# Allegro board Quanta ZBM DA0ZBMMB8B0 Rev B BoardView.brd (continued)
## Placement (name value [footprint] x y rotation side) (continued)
R3C22  20K_5%_2  [R0201-SMT-TEST]  87.97 42.06 0 top
R3C23  20K_5%_2  [R0201-SMT-TEST]  87.97 41.3 0 top
R3F3  56_1%_4  [R0402]  124.96 78.79 90 top
R3F4  100_1%_4  [R0402]  123.84 79.01 90 top
R3F13  *Short_0402  [S0402]  124.96 81.17 270 top
R4  0_5%_2  [R0201-SMT-TEST]  71.75 65.19 315 bottom
R4E63  *4.7K_1%_2  [R0201-SMT-TEST]  96.28 69.91 0 bottom
R4F20  *20K_1%_2  [R0201-SMT-TEST]  94.89 69.91 180 top
R4F23  100K_1%_2  [R0201-SMT-TEST]  94.76 70.62 0 top
R5  0_5%_2  [R0201-SMT-TEST]  72.92 66.36 315 bottom
R5F9  113_1%_2  [R0201-SMT-TEST]  105.9 77.35 180 top
R5G69  *1K_1%_2  [R0201-SMT-TEST]  119.65 76.68 270 top
R5M19  1K_1%_2  [R0201-SMT-TEST]  128.77 80.55 180 top
R6  0_5%_2  [R0201-SMT-TEST]  74.44 58.91 45 bottom
R6C1  100K_1%_2  [R0201-SMT-TEST]  103.14 73.37 270 bottom
R6D29  *4.7K_1%_2  [R0201-SMT-TEST]  94.76 67.37 180 top
R6D34  100K_1%_2  [R0201-SMT-TEST]  92.73 68.29 0 top
R6D38  *20K_1%_2  [R0201-SMT-TEST]  96.03 66.49 270 top
R6D39  *4.7K_1%_2  [R0201-SMT-TEST]  100.88 73.09 270 bottom
R6D40  *4.7K_1%_2  [R0201-SMT-TEST]  103.9 73.37 270 bottom
R6D41  *4.7K_1%_2  [R0201-SMT-TEST]  96.79 66.49 90 top
R6D42  *4.7K_1%_2  [R0201-SMT-TEST]  101.62 73.09 270 bottom
R6D46  *4.7K_1%_2  [R0201-SMT-TEST]  102.38 73.09 270 bottom
R6D66  *4.7K_1%_2  [R0201-SMT-TEST]  97.02 73.67 270 bottom
R6D67  *4.7K_1%_2  [R0201-SMT-TEST]  96.08 73.34 0 bottom
R6D82  *4.7K_1%_2  [R0201-SMT-TEST]  99.08 73.82 0 bottom
R6D84  20K_1%_2  [R0201-SMT-TEST]  98.11 73.67 270 bottom
R6D85  *20K_1%_2  [R0201-SMT-TEST]  99.97 72.58 180 bottom
R6D88  0_5%_2  [R0201-SMT-TEST]  107.21 60.97 0 bottom
R6E3  60.4_1%_2  [R0201-SMT-TEST]  112.23 77.55 90 top
R6E5  49.9_1%_2  [R0201-SMT-TEST]  111.47 77.55 90 top
R6F1  150_1%_2  [R0201-SMT-TEST]  137.05 72.96 270 top
R6F3  49.9_1%_2  [R0201-SMT-TEST]  130.1 76.5 90 top
R7  0.01_1%_6  [R0603]  95.97 73.61 270 top
R7D9  49.9_1%_2  [R0201-SMT-TEST]  96.86 49.81 180 top
R7D24  *20K_1%_2  [R0201-SMT-TEST]  93.31 47.02 90 top
R7D25  *4.7K_1%_2  [R0201-SMT-TEST]  96.28 69.91 270 top
R7D26  *4.7K_1%_2  [R0201-SMT-TEST]  92.55 47.02 270 top
R7D35  *4.7K_1%_2  [R0201-SMT-TEST]  96.64 68.64 0 top
R7D40  *4.7K_1%_2  [R0201-SMT-TEST]  97.15 70.55 90 top
R8  0_5%_2  [R0201-SMT-TEST]  92.16 75.8 180 top
R8A7  *4.7K_1%_2  [R0201-SMT-TEST]  96.28 68.72 0 bottom
R9  100K_5%_2  [R0201-SMT-TEST]  85.94 44.35 0 top
R10  *Short_0201  [S0201]  93.05 45.24 270 top
R11  *2.2K_5%_2  [R0201-SMT-TEST]  94.89 63.89 270 bottom
R12  1M_1%_2  [R0201-SMT-TEST]  160.62 19.98 0 top
R13  *Short_0201  [S0201]  57.96 39.67 0 bottom
R17  0_5%_2  [R0201-SMT-TEST]  113.94 83.75 90 top
R18  *Short_0201  [S0201]  96.81 46.25 0 top
R19  *Short_0201  [S0201]  96.08 45.37 0 top
R20  10K_1%_2  [R0201-SMT-TEST]  108.55 53.9 270 bottom
R21  0_5%_2  [R0201-SMT-TEST]  73.81 67.24 315 bottom
R22  100K_1%_2  [R0201-SMT-TEST]  105.98 66.07 270 bottom
R23  100K_1%_2  [R0201-SMT-TEST]  106.08 67.72 90 bottom
R24  *0_5%_2  [R0201-SMT-TEST]  79.94 75.54 315 bottom
R25  0_5%_2  [R0201-SMT-TEST]  70.63 66.1 315 bottom
R26  0_5%_2  [R0201-SMT-TEST]  72.28 65.72 315 bottom
R27  0_5%_2  [R0201-SMT-TEST]  75.08 58.28 45 bottom
R28  0_5%_2  [R0201-SMT-TEST]  114.7 83.75 90 top
R29  0_5%_2  [R0201-SMT-TEST]  72.79 68.26 315 bottom
R30  **20K_1%_2  [R0201-SMT-TEST]  73.17 69.91 315 bottom
R31  *0_5%_2  [R0201-SMT-TEST]  74.57 69.78 315 bottom
R32  10K_1%_2  [R0201-SMT-TEST]  80.48 76.08 315 bottom
R33  *1K_1%_2  [R0201-SMT-TEST]  74.19 68.77 225 bottom
R34  100_1%_2  [R0201-SMT-TEST]  110.48 76.49 0 top
R35  *0_5%_2  [R0201-SMT-TEST]  108.2 60.97 180 bottom
R36  10K_1%_2  [R0201-SMT-TEST]  124.1 83.25 180 top
R37  1K_1%_2  [R0201-SMT-TEST]  71.87 67.43 225 bottom
R38  *0_5%_2  [R0201-SMT-TEST]  70 65.47 135 bottom
R39  *Short_0201  [S0201]  93.31 55.02 90 top
R40  *10K_1%_2  [R0201-SMT-TEST]  70.38 63.82 135 bottom
R41  *2.2K_1%_2  [R0201-SMT-TEST]  89.65 68.74 180 bottom
R42  *1K_1%_2  [R0201-SMT-TEST]  92.68 73.16 180 bottom
R43  *1K_1%_2  [R0201-SMT-TEST]  91.86 71.92 90 bottom
R44  *1K_1%_2  [R0201-SMT-TEST]  90.95 68.77 180 bottom
R45  *1K_1%_2  [R0201-SMT-TEST]  88.28 68.13 180 bottom
R46  100_1%_2  [R0201-SMT-TEST]  117.82 76.61 270 top
R47  *2.2K_1%_2  [R0201-SMT-TEST]  89.76 69.45 180 bottom
R48  *0_1%_4  [R0402]  90.67 70.29 180 bottom
R49  100K_1%_2  [R0201-SMT-TEST]  96.21 60.82 180 top
R50  33.2_1%_2  [R0201-SMT-TEST]  104.16 57.14 90 bottom
R51  100K_1%_2  [R0201-SMT-TEST]  165.37 27.7 270 top
R52  100K_1%_2  [R0201-SMT-TEST]  164.1 28.89 270 top
R53  33_1%_2  [R0201-SMT-TEST]  176.33 31.89 270 bottom
R54  33_1%_2  [R0201-SMT-TEST]  176.28 21.79 90 bottom
R55  100K_1%_2  [R0201-SMT-TEST]  180.73 20.71 0 bottom
R56  33_1%_2  [R0201-SMT-TEST]  177.96 32.02 180 bottom
R57  33_1%_2  [R0201-SMT-TEST]  178.22 21.79 90 bottom
R58  *33_1%_2  [R0201-SMT-TEST]  175.44 31.89 270 bottom
R59  100K_1%_2  [R0201-SMT-TEST]  175.2 21.79 90 bottom
R60  10K_1%_2  [R0201-SMT-TEST]  169.56 21.22 0 top
R61  1M_1%_2  [R0201-SMT-TEST]  170.96 21.22 0 top
R62  100K_1%_2  [R0201-SMT-TEST]  164.66 27.7 270 top
R63  1M_1%_2  [R0201-SMT-TEST]  164.38 25 270 top
R64  1M_1%_2  [R0201-SMT-TEST]  166.69 24.93 90 bottom
R65  5.1K_1%_2  [R0201-SMT-TEST]  170.79 23.39 270 top
R66  1M_1%_2  [R0201-SMT-TEST]  169.56 23.51 0 top
R67  10K_1%_2  [R0201-SMT-TEST]  169.74 24.4 0 top
R68  1K_1%_2  [R0201-SMT-TEST]  167.33 25.16 270 top
R69  10K_1%_2  [R0201-SMT-TEST]  169.56 19.7 0 top
R70  10_1%_2  [R0201-SMT-TEST]  94.17 58.29 180 top
R71  30.9K_1%_2  [R0201-SMT-TEST]  166.69 16.95 90 top
R72  1M_1%_2  [R0201-SMT-TEST]  161.23 21.54 180 top
R73  100K_1%_2  [R0201-SMT-TEST]  160.62 19.26 0 top
R74  1M_1%_2  [R0201-SMT-TEST]  161.23 22.26 0 top
R75  100K_1%_2  [R0201-SMT-TEST]  166.05 17.91 180 bottom
R76  UR@0_5%_2  [R0201-SMT-TEST]  173.5 30.75 180 top
R77  UR@0_5%_2  [R0201-SMT-TEST]  177.09 31.89 270 bottom
R78  UR@0_5%_2  [R0201-SMT-TEST]  177.06 21.79 90 bottom
R79  UR@0_5%_2  [R0201-SMT-TEST]  179 21.79 90 bottom
R80  100K_1%_2  [R0201-SMT-TEST]  73.5 47.02 270 top
R81  *Short_0201  [S0201]  25.55 43.75 180 top
R82  *Short_0201  [S0201]  21.61 32.32 180 top
R83  *Short_0201  [S0201]  25.55 41.36 180 top
R84  10K_5%_2  [R0201-SMT-TEST]  24.4 38.8 180 top
R85  *Short_0201  [S0201]  16.78 47.31 270 top
R86  *Short_0201  [S0201]  22.62 34.22 90 top
R87  *Short_0201  [S0201]  6.11 34.48 90 top
R88  1M_1%_2  [R0201-SMT-TEST]  16.78 42.48 90 top
R89  2.2K_5%_2  [R0201-SMT-TEST]  24.4 40.78 0 top
R90  *Short_0201  [S0201]  18.81 46.14 0 top
R91  *Short_0201  [S0201]  18.81 45.4 0 top
R92  *Short_0402  [S0402]  15.61 38.32 90 top
R93  *Short_0402  [S0402]  22.88 45.02 270 top
R94  *Short_0402  [S0402]  16.02 36.26 90 top
R95  2.2K_5%_2  [R0201-SMT-TEST]  24.4 40.07 0 top
R96  *Short_0201  [S0201]  16.27 43.37 90 bottom
R97  *Short_0201  [S0201]  17.04 44.26 180 bottom
R98  SW@0_5%_2  [R0201-SMT-TEST]  123.29 20.18 90 top
R99  10K_1%_2  [R0201-SMT-TEST]  124.45 21.67 270 top
R102  UR@1K_1%_2  [R0201-SMT-TEST]  167.53 27.37 180 top
R103  2.2K_5%_2  [R0201-SMT-TEST]  102.14 68.97 0 bottom
R105  *4.7K_1%_2  [R0201-SMT-TEST]  107.56 63.78 180 bottom
R107  100K_1%_2  [R0201-SMT-TEST]  106.69 64.06 90 bottom
R109  100K_1%_2  [R0201-SMT-TEST]  34.81 27.71 180 bottom
R110  0_5%_4  [R0402]  175.66 55.94 270 bottom
R111  10K_1%_2  [R0201-SMT-TEST]  34.76 25.97 270 bottom
R112  200K_1%_2  [R0201-SMT-TEST]  34 25.97 90 bottom
R113  *100K_1%_2  [R0201-SMT-TEST]  42.61 16.12 0 top
R114  *100K_1%_2  [R0201-SMT-TEST]  174.46 57.71 90 top
R116  *100K_1%_2  [R0201-SMT-TEST]  32.26 24.32 270 bottom
R117  100K_1%_2  [R0201-SMT-TEST]  104.92 70.93 0 bottom
R118  49.9_1%_2  [R0201-SMT-TEST]  42.62 18.1 180 top
R119  49.9_1%_2  [R0201-SMT-TEST]  42.62 18.89 180 top
R120  100K_1%_2  [R0201-SMT-TEST]  35.52 25.97 90 bottom
R121  2.2K_1%_2  [R0201-SMT-TEST]  150.16 23.05 0 bottom
R123  2.2K_1%_2  [R0201-SMT-TEST]  150.16 23.81 0 bottom
R125  0_5%_4  [R0402]  156.99 27.57 90 bottom
R126  2.2K_1%_2  [R0201-SMT-TEST]  159.91 29.4 180 top
R128  2.2K_1%_2  [R0201-SMT-TEST]  159.91 28.26 180 top
R129  2.2_1%_6  [R0603]  177.08 58.45 270 top
R130  2.2K_1%_2  [R0201-SMT-TEST]  153.64 30.71 270 top
R131  2.2_1%_6  [R0603]  174.97 50.95 270 top
R132  2.2K_1%_2  [R0201-SMT-TEST]  152.88 30.71 270 top
R133  113K_1%_2  [R0201-SMT-TEST]  181.7 49.18 90 bottom
R134  *1K_1%_2  [R0201-SMT-TEST]  160.34 24.87 180 top
R135  19.6K_1%_2  [R0201-SMT-TEST]  181.7 49.18 270 top
R136  0_5%_2  [R0201-SMT-TEST]  155.34 17.04 90 bottom
R137  *1K_1%_2  [R0201-SMT-TEST]  160.34 25.63 180 top
R138  200_1%_2  [R0201-SMT-TEST]  181.7 48.03 270 top
R139  1K_1%_2  [R0201-SMT-TEST]  157.07 25.12 270 bottom
R140  1K_1%_2  [R0201-SMT-TEST]  154.83 26.68 270 bottom
R141  1.87K_1%_2  [R0201-SMT-TEST]  180.94 49.18 90 bottom
R142  100K_1%_2  [R0201-SMT-TEST]  160 26.63 270 top
R143  953_1%_2  [R0201-SMT-TEST]  180.94 49.18 90 top
R144  2.2K_5%_2  [R0201-SMT-TEST]  102.39 69.86 270 bottom
R145  100_1%_2  [R0201-SMT-TEST]  156.48 17.33 270 top
R146  100K_1%_2  [R0201-SMT-TEST]  133.57 70.26 0 bottom
R147  100K_1%_2  [R0201-SMT-TEST]  133.57 69.5 0 bottom
R148  0_5%_2  [R0201-SMT-TEST]  162.45 70.55 180 top
R149  0_5%_2  [R0201-SMT-TEST]  163.47 70.55 0 top
R150  33.2_1%_2  [R0201-SMT-TEST]  102.13 56.4 90 bottom
R151  33.2_1%_2  [R0201-SMT-TEST]  104.92 57.14 90 bottom
R152  499K_1%_2  [R0201-SMT-TEST]  164.81 31.41 0 top
R153  100K_1%_2  [R0201-SMT-TEST]  170.58 31.51 180 top
R154  100K_1%_2  [R0201-SMT-TEST]  162.45 16.4 180 top
R155  UR@1M_1%_2  [R0201-SMT-TEST]  170.79 25.77 180 bottom
R156  10_1%_2  [R0201-SMT-TEST]  73.5 42.83 0 top
R157  10_1%_2  [R0201-SMT-TEST]  73.5 40.41 0 top
R158  10_1%_2  [R0201-SMT-TEST]  73.68 37.65 270 top
R159  10_1%_2  [R0201-SMT-TEST]  74.51 44.22 90 top
R160  10_1%_2  [R0201-SMT-TEST]  73.5 43.59 0 top
R161  10_1%_2  [R0201-SMT-TEST]  73.5 42.06 0 top
R162  10_1%_2  [R0201-SMT-TEST]  73.37 39.52 90 top
R163  10_1%_2  [R0201-SMT-TEST]  72.15 37.65 270 top
R164  10_1%_2  [R0201-SMT-TEST]  73.5 48.03 270 top
R165  10_1%_2  [R0201-SMT-TEST]  73.5 49.18 270 top
R166  10_1%_2  [R0201-SMT-TEST]  73.37 45.37 90 top
R167  20K_1%_2  [R0201-SMT-TEST]  75.15 42.44 180 top
R168  20K_1%_2  [R0201-SMT-TEST]  74.59 40.41 180 top
R169  *Short_0201  [S0201]  74.26 47.02 90 top
R170  20K_1%_2  [R0201-SMT-TEST]  74.44 37.65 270 top
R171  20K_1%_2  [R0201-SMT-TEST]  75.27 44.22 90 top
R172  20K_1%_2  [R0201-SMT-TEST]  75.15 43.21 180 top
R173  20K_1%_2  [R0201-SMT-TEST]  75.15 41.68 180 top
R174  20K_1%_2  [R0201-SMT-TEST]  74.26 48.03 90 top
R175  20K_1%_2  [R0201-SMT-TEST]  74.13 39.52 90 top
R176  20K_1%_2  [R0201-SMT-TEST]  74.13 46 270 top
R177  20K_1%_2  [R0201-SMT-TEST]  72.92 37.65 270 top
R178  20K_1%_2  [R0201-SMT-TEST]  74.26 49.18 270 top
R179  0_5%_6  [R0603]  23.05 29.22 0 top
R180  0_5%_2  [R0201-SMT-TEST]  21.16 17.71 180 top
R181  *Short_0603  [S0603]  20.81 28.56 270 top
R182  *Short_0603  [S0603]  26.51 24.44 270 top
R183  1M_5%_2  [R0201-SMT-TEST]  22.18 17.71 180 top
R184  *5.11K_1%_2  [R0201-SMT-TEST]  17.09 39.56 90 bottom
R185  *5.11K_1%_2  [R0201-SMT-TEST]  16.02 36.64 0 bottom
R186  0_5%_6  [R0603]  27.45 19.98 180 top
R187  0_5%_2  [R0201-SMT-TEST]  22.32 9.33 270 top
R188  100K_1%_2  [R0201-SMT-TEST]  22.62 43.06 180 top
R189  *Short_0603  [S0603]  24.72 18.94 270 top
R190  *Short_0603  [S0603]  29.36 15.17 270 top
R191  *NSW@0_5%_2  [R0201-SMT-TEST]  122.5 20.68 90 top
R192  SW@0_5%_2  [R0201-SMT-TEST]  126.06 21.57 180 top
R193  *NSW@0_5%_2  [R0201-SMT-TEST]  125.17 21.67 270 top
R194  1K_1%_2  [R0201-SMT-TEST]  16.46 17.84 90 top
R195  402_1%_2  [R0201-SMT-TEST]  15.7 17.84 90 top
R196  200_1%_2  [R0201-SMT-TEST]  14.94 17.84 90 top
R199  100K_1%_2  [R0201-SMT-TEST]  161.49 24.9 270 bottom
R200  100K_1%_2  [R0201-SMT-TEST]  51.07 59.88 270 bottom
R201  10K_1%_2  [R0201-SMT-TEST]  53.74 58.74 180 bottom
R202  10K_1%_2  [R0201-SMT-TEST]  156.18 25.26 180 bottom
R203  *Short_0201  [S0201]  59.3 33.38 90 top
R204  5.11K_1%_2  [R0201-SMT-TEST]  189.79 33.88 0 bottom
R205  22_5%_2  [R0201-SMT-TEST]  15.51 28.56 90 top
R206  22_5%_2  [R0201-SMT-TEST]  15.51 29.55 90 top
R207  22_5%_2  [R0201-SMT-TEST]  15.51 23 90 top
R208  22_5%_2  [R0201-SMT-TEST]  15.51 24.02 90 top
R209  22_5%_2  [R0201-SMT-TEST]  15.51 25.03 90 top
R210  100K_5%_2  [R0201-SMT-TEST]  29.79 67.73 270 top
R211  100K_5%_2  [R0201-SMT-TEST]  31.97 67.73 90 top
R212  0_5%_2  [R0201-SMT-TEST]  164.47 16.85 270 top
R213  0_5%_2  [R0201-SMT-TEST]  163.71 16.85 270 top
R214  0_5%_2  [R0201-SMT-TEST]  42.21 70.15 0 top
R215  0_5%_2  [R0201-SMT-TEST]  42.21 69.38 0 top
R216  *0_5%_2  [R0201-SMT-TEST]  43.63 70.15 0 top
R217  *0_5%_2  [R0201-SMT-TEST]  43.63 69.38 0 top
R218  0_5%_2  [R0201-SMT-TEST]  35.86 70.18 180 top
R219  0_5%_2  [R0201-SMT-TEST]  35.86 69.4 180 top
R220  220K_1%_2  [R0201-SMT-TEST]  8.58 69.58 180 bottom
R221  220K_1%_2  [R0201-SMT-TEST]  9.58 69.58 0 bottom
R222  220K_1%_2  [R0201-SMT-TEST]  8.37 71.36 90 top
R223  220K_1%_2  [R0201-SMT-TEST]  8.37 70.34 270 top
R224  2_1%_4  [R0402]  52.98 9.65 90 top
R225  *0_5%_2  [R0201-SMT-TEST]  59.33 14.16 90 top
R226  0_5%_4  [R0402]  53.95 9.65 270 top
R227  1.4K_1%_4  [R0402]  57.17 15.17 0 bottom
R228  0_5%_4  [R0402]  82.44 17.97 270 bottom
R229  2_1%_4  [R0402]  83.66 18 90 bottom
R230  100K_1%_2  [R0201-SMT-TEST]  47.06 58.48 180 top
R231  *0_5%_2  [R0201-SMT-TEST]  51.14 55.78 180 top
R232  0_5%_2  [R0201-SMT-TEST]  180.94 48.03 270 top
R233  1.37K_1%_2  [R0201-SMT-TEST]  180.18 49.18 90 bottom
R234  100K_1%_2  [R0201-SMT-TEST]  183.99 42.81 90 top
R235  1.15K_1%_2  [R0201-SMT-TEST]  180.18 49.18 270 top
R236  22_1%_2  [R0201-SMT-TEST]  180.18 48.03 270 top
R237  174K_1%_2  [R0201-SMT-TEST]  179.97 57.81 90 bottom
R238  0.02_1%_6  [R0603]  178.07 33.3 0 top
R239  0_5%_2  [R0201-SMT-TEST]  185.51 39.78 270 top
R240  *Short_0201  [S0201]  60.09 33.38 90 top
R241  100_1%_4  [R0402]  50.44 54.93 270 bottom
R242  100_1%_4  [R0402]  49.42 54.93 90 bottom
R243  0.01_1%_6  [R0603]  179.79 36.73 90 top
R244  0.1_1%_6  [R0603]  187.41 34.44 180 top
R245  0.002_1%_12  [R1206]  161.82 47.38 315 top
R246  0_1%_6  [R0603]  77.18 51.03 0 top
R247  0.02_1%_6  [R0603]  84.73 57.04 270 top
R248  0.02_1%_6  [R0603]  34.89 55.18 270 top
R249  0.05_1%_6  [R0603]  36.34 55.18 270 top
R250  0.1_1%_6  [R0603]  31.92 55.18 270 top
R251  100_1%_2  [R0201-SMT-TEST]  119.58 82.87 180 top
R252  0.1_1%_4  [R0402]  30.67 53.86 90 top
R253  100K_1%_2  [R0201-SMT-TEST]  64.53 67.45 0 top
R254  100K_1%_2  [R0201-SMT-TEST]  65.45 65.19 90 top
R255  220K_1%_2  [R0201-SMT-TEST]  92.45 21.09 270 bottom
R256  499K_1%_2  [R0201-SMT-TEST]  97.55 21.02 270 bottom
R257  *0_5%_2  [R0201-SMT-TEST]  92.45 20.08 270 bottom
R258  0.02_1%_8  [R0805]  43.83 44.77 90 top
R259  0.01_1%_8  [R0805]  46.58 35.88 0 top
R260  *100K_1%_2  [R0201-SMT-TEST]  41.21 44.98 270 bottom
R261  100K_1%_2  [R0201-SMT-TEST]  42.76 36.22 270 top
R262  1K_1%_2  [R0201-SMT-TEST]  38.19 45.37 90 top
R263  1K_1%_2  [R0201-SMT-TEST]  42 36.22 90 top
R264  8.45K_1%_2  [R0201-SMT-TEST]  180.18 58.7 0 bottom
R265  205_1%_2  [R0201-SMT-TEST]  180.87 57.08 180 bottom
R266  0.01_1%_8  [R0805]  32.73 47.33 270 top
R267  0.01_1%_8  [R0805]  29.78 37.1 0 top
R268  100K_NTC_4_1%  [R0402]  164 66.64 0 top
R269  19.1K_1%_2  [R0201-SMT-TEST]  183.6 52.99 0 bottom
R270  7.68K_1%_2  [R0201-SMT-TEST]  184.27 54.65 270 bottom
R271  110K_1%_2  [R0201-SMT-TEST]  179.24 57.81 90 bottom
R272  0.05_1%_6  [R0603]  70.29 24.24 270 top
R273  100K_1%_2  [R0201-SMT-TEST]  74.19 27.75 180 top
R274  100K_NTC_4_1%  [R0402]  173.65 62.57 270 top
R275  13.7K_1%_2  [R0201-SMT-TEST]  183.6 52.22 180 bottom
R276  0.01_1%_8  [R0805]  78.58 35.46 270 top
R277  60.4K_1%_2  [R0201-SMT-TEST]  73.75 23.23 90 top
R278  30.1K_1%_2  [R0201-SMT-TEST]  72.99 23.23 270 top
R279  51_1%_2  [R0201-SMT-TEST]  118.38 83.63 180 top
R280  51_1%_2  [R0201-SMT-TEST]  115.46 83.75 270 top
R281  100_1%_2  [R0201-SMT-TEST]  119.65 83.63 0 top
R282  51_1%_2  [R0201-SMT-TEST]  120.92 83.63 0 top
R283  *51_1%_2  [R0201-SMT-TEST]  117.11 83.63 180 top
R284  *0_5%_2  [R0201-SMT-TEST]  125.17 20.08 270 top
R285  1M_1%_2  [R0201-SMT-TEST]  152.55 17.42 270 top
R286  100K_1%_2  [R0201-SMT-TEST]  153.43 17.46 0 top
R287  100K_1%_2  [R0201-SMT-TEST]  20.56 30.85 0 top
R288  28.7K_1%_2  [R0201-SMT-TEST]  18.9 27.21 270 top
R289  0.05_1%_6  [R0603]  17.02 27.61 90 top
R290  *Short_0201  [S0201]  57.21 36 180 bottom
R291  100K_1%_2  [R0201-SMT-TEST]  58.95 39.67 0 bottom
R292  100K_1%_2  [R0201-SMT-TEST]  58.08 36.33 90 bottom
R293  7.5K_1%_2  [R0201-SMT-TEST]  60.98 35.73 90 bottom
R294  10K_1%_2  [R0201-SMT-TEST]  60.98 36.72 90 bottom
R295  0_5%_2  [R0201-SMT-TEST]  184.63 39.05 270 top
R296  100K_1%_2  [R0201-SMT-TEST]  85.29 15.31 90 top
R297  100K_1%_2  [R0201-SMT-TEST]  93.07 13 0 top
R298  100K_1%_2  [R0201-SMT-TEST]  40.66 47.33 90 top
R299  100K_1%_2  [R0201-SMT-TEST]  41.42 47.33 90 top
R300  *Short_0201  [S0201]  41.29 46 270 top
R301  *0_5%_2  [R0201-SMT-TEST]  42.02 46 90 top
R302  TS@1M_1%_2  [R0201-SMT-TEST]  32.84 52.87 180 top
R303  *Short_0201  [S0201]  176.29 29.73 180 top
R304  0.02_1%_6  [R0603]  40 54.75 270 top
R305  *75K_1%_2  [R0201-SMT-TEST]  98.77 58.12 90 bottom
R311  *PSYS  [R0201-SMT-TEST]  183.22 49.18 270 top
R313  *Short_0201  [S0201]  173.6 31.51 0 bottom
R314  100K_1%_2  [R0201-SMT-TEST]  94.32 54.74 0 top
R315  100_1%_2  [R0201-SMT-TEST]  169.56 18.94 180 top
R316  2.2K_5%_2  [R0201-SMT-TEST]  95.75 71.07 0 top
R317  0_5%_2  [R0201-SMT-TEST]  149.19 16.57 180 top
R318  100_1%_4  [R0402]  178.27 49.3 270 top
R319  100K_1%_2  [R0201-SMT-TEST]  43.65 35.99 180 top
R320  51.1K_1%_2  [R0201-SMT-TEST]  90.01 34.19 270 top
R321  47K_NTC_4_1%  [R0402]  90.01 32.79 90 top
R322  51.1K_1%_2  [R0201-SMT-TEST]  140.61 72.91 270 top
R323  47K_NTC_4_1%  [R0402]  140.61 71.51 90 top
R324  2.2K_5%_2  [R0201-SMT-TEST]  95.75 71.83 0 top
R325  2.2K_5%_2  [R0201-SMT-TEST]  96.28 60.47 0 bottom
R326  2.2K_5%_2  [R0201-SMT-TEST]  96.28 61.23 0 bottom
R327  2.2K_5%_2  [R0201-SMT-TEST]  96.79 62.75 0 bottom
R328  2.2K_5%_2  [R0201-SMT-TEST]  96.79 61.99 0 bottom
R329  2.2K_5%_2  [R0201-SMT-TEST]  99.08 61.15 0 bottom
R330  2.2K_5%_2  [R0201-SMT-TEST]  99.08 61.91 0 bottom
R331  33_5%_2  [R0201-SMT-TEST]  99.66 58.19 0 bottom
R332  33_5%_2  [R0201-SMT-TEST]  100.73 61.28 0 bottom
R333  33_5%_2  [R0201-SMT-TEST]  104.79 58.81 0 bottom
R334  33_5%_2  [R0201-SMT-TEST]  98.77 57.05 90 bottom
R335  33_5%_2  [R0201-SMT-TEST]  100.86 64.3 0 bottom
R336  33_5%_2  [R0201-SMT-TEST]  100.86 59.12 0 bottom
R337  33_5%_2  [R0201-SMT-TEST]  103.78 58.81 0 bottom
R338  0_5%_2  [R0201-SMT-TEST]  88.99 43.71 90 top
R339  100K_5%_2  [R0201-SMT-TEST]  90.01 43.71 90 top
R340  100K_1%_2  [R0201-SMT-TEST]  92.29 45.24 90 top
R341  *100K_1%_2  [R0201-SMT-TEST]  95.34 54.74 0 top
R343  10_1%_2  [R0201-SMT-TEST]  96.21 59.32 180 top
R344  10_1%_2  [R0201-SMT-TEST]  93.82 57.43 180 top
R345  10_1%_6  [R0603]  37.61 37.02 270 top
R346  10_1%_6  [R0603]  36.41 46.66 0 top
R347  2.2_1%_6  [R0603]  79.27 24.95 180 top
R352  10_1%_2  [R0201-SMT-TEST]  96.61 57.05 180 top
R353  49.9_1%_2  [R0201-SMT-TEST]  95.85 57.82 180 top
R354  10K_1%_2  [R0201-SMT-TEST]  101.69 45.67 0 top
R355  100K_1%_2  [R0201-SMT-TEST]  99.81 63.37 90 bottom
R356  *Short_0201  [S0201]  169.56 20.46 180 top
R357  *0_5%_2  [R0201-SMT-TEST]  170.96 20.46 180 top
R360  0_5%_2  [R0201-SMT-TEST]  170.96 19.7 180 top
R362  3.9_5%_4  [R0402]  181.76 53.4 0 bottom
R363  100_1%_2  [R0201-SMT-TEST]  64.79 18.1 0 bottom
R364  2.2_1%_6  [R0603]  175.16 55.85 0 top
R365  10K_5%_2  [R0201-SMT-TEST]  181.7 57.64 90 top
R366  *Short_0201  [S0201]  95.01 64.66 180 top
R367  *Short_0201  [S0201]  96.28 64.66 180 top
R368  100K_5%_2  [R0201-SMT-TEST]  92.8 44.1 180 bottom
R369  *Short_0201  [S0201]  96.28 63.89 180 top
R370  1M_1%_2  [R0201-SMT-TEST]  37.03 64.48 90 top
R371  1M_1%_2  [R0201-SMT-TEST]  37.74 64.48 90 top
R372  1M_1%_2  [R0201-SMT-TEST]  38.88 64.01 180 top
R373  1M_1%_2  [R0201-SMT-TEST]  39.9 64.01 0 top
R375  100K_5%_2  [R0201-SMT-TEST]  25.81 58.52 0 top
R377  0_1%_4  [R0402]  177.86 41.27 0 top
R378  1M_1%_2  [R0201-SMT-TEST]  83.79 12.13 270 top
R379  10K_1%_2  [R0201-SMT-TEST]  96.79 21.02 270 bottom
R380  10K_1%_2  [R0201-SMT-TEST]  96.13 61.61 0 top
R381  10K_1%_2  [R0201-SMT-TEST]  94.35 59.32 0 top
R382  10K_1%_2  [R0201-SMT-TEST]  96.21 60.11 0 top
R383  10K_1%_2  [R0201-SMT-TEST]  94.35 61.78 0 top
R384  75K_1%_2  [R0201-SMT-TEST]  95.78 49.85 0 top
R385  33_5%_2  [R0201-SMT-TEST]  96.64 67.7 0 top
R386  33_5%_2  [R0201-SMT-TEST]  100.17 45.49 180 top
R387  *1K_1%_2  [R0201-SMT-TEST]  98.64 45.49 0 top
R389  33_5%_2  [R0201-SMT-TEST]  101.87 60.26 180 bottom
R390  15_1%_2  [R0201-SMT-TEST]  94.83 56.67 180 top
R391  15_1%_2  [R0201-SMT-TEST]  96.61 56.29 180 top
R392  100K_5%_2  [R0201-SMT-TEST]  96.36 53.24 0 top
R393  100K_5%_2  [R0201-SMT-TEST]  96.36 54 0 top
R394  220_1%_2  [R0201-SMT-TEST]  119.72 79.5 90 top
R395  *Short_0201  [S0201]  168.34 25.16 270 top
R397  33_5%_2  [R0201-SMT-TEST]  97.17 59.37 270 bottom
R398  1_5%_4  [R0402]  180.1 27.45 90 top
R399  0_1%_4  [R0402]  179.09 27.42 90 top
R400  *Short_0201  [S0201]  102.89 71.67 180 bottom
R401  *Short_0201  [S0201]  97.05 72.71 90 top
R402  100K_1%_2  [R0201-SMT-TEST]  106.13 57.18 90 bottom
R403  100K_1%_2  [R0201-SMT-TEST]  104.31 70.01 0 bottom
R404  10K_1%_2  [R0201-SMT-TEST]  91.66 47.91 90 top
R405  1K_1%_2  [R0201-SMT-TEST]  128.62 77.79 0 top
R406  *1K_1%_2  [R0201-SMT-TEST]  128.62 77.02 180 top
R407  1K_1%_2  [R0201-SMT-TEST]  77.23 72.83 315 bottom
R408  1K_1%_2  [R0201-SMT-TEST]  77.79 73.39 315 bottom
R409  1K_1%_2  [R0201-SMT-TEST]  78.33 73.93 315 bottom
R410  1K_1%_2  [R0201-SMT-TEST]  78.87 74.47 315 bottom
R411  1K_1%_2  [R0201-SMT-TEST]  75.33 70.55 315 bottom
R412  1K_1%_2  [R0201-SMT-TEST]  79.41 75 315 bottom
R413  *100K_1%_2  [R0201-SMT-TEST]  92.04 70.77 180 top
R414  100K_1%_2  [R0201-SMT-TEST]  92.04 71.5 0 top
R415  *100K_1%_2  [R0201-SMT-TEST]  92.91 70.9 90 top
R416  100K_1%_2  [R0201-SMT-TEST]  94.75 71.4 180 top
R417  *100K_1%_2  [R0201-SMT-TEST]  94.84 69.1 180 top
R418  100K_1%_2  [R0201-SMT-TEST]  94.84 68.34 180 top
R419  *100K_1%_2  [R0201-SMT-TEST]  93.77 70.5 180 top
R420  100K_1%_2  [R0201-SMT-TEST]  93.57 69.79 0 top
R422  *10K_1%_2  [R0201-SMT-TEST]  42.61 16.91 180 top
R423  100K_1%_2  [R0201-SMT-TEST]  156.11 21.93 270 bottom
R424  100K_5%_2  [R0201-SMT-TEST]  15.51 30.54 90 top
R425  680_5%_4  [R0402]  180.4 58.14 270 top
R426  36.5K_1%_4  [R0402]  182.05 55.78 270 bottom
R427  1.5K_5%_6  [R0603]  179.34 59.73 180 top
R428  8.45K_1%_4  [R0402]  182.39 57.47 180 bottom
R429  1.5K_5%_6  [R0603]  178.02 61.75 270 top
R430  1.5K_5%_6  [R0603]  176.49 61.75 90 top
R431  *0_5%_2  [R0201-SMT-TEST]  51.14 55.02 0 top
R432  5.1_1%_6  [R0603]  53.61 62.16 90 top
R433  237K_1%_2  [R0201-SMT-TEST]  47.57 59.62 180 top
R434  *Short_0402  [S0402]  54.63 54.67 180 top
R435  0_1%_4  [R0402]  53.36 56.2 180 bottom
R436  *Short_0402  [S0402]  56.28 58.61 270 top
R437  80.6K_1%_2  [R0201-SMT-TEST]  181.25 44.72 270 top
R438  10K_1%_2  [R0201-SMT-TEST]  46.88 54.47 0 top
R439  17.8K_1%_4  [R0402]  49.37 55.1 270 top
R440  1.43K_1%_2  [R0201-SMT-TEST]  50.26 55.18 90 top
R441  620K_1%_4  [R0402]  185.13 40.92 180 top
R442  *0603  [R0603]  67.46 56.15 270 bottom
R443  5.1K_1%_2  [R0201-SMT-TEST]  181.06 37.36 0 top
R444  48.7K_1%_2  [R0201-SMT-TEST]  181.65 36.6 0 top
R445  10K_1%_2  [R0201-SMT-TEST]  183.1 37.75 0 top
R446  21.5K_1%_2  [R0201-SMT-TEST]  183.1 36.22 180 top
R447  5.1_1%_4  [R0402]  73.11 28.47 90 top
R448  *0_5%_2  [R0201-SMT-TEST]  162.78 71.78 90 top
R449  0_5%_2  [R0201-SMT-TEST]  162.9 73.2 270 top
R450  0_5%_2  [R0201-SMT-TEST]  164.05 71.78 90 top
R451  *0_5%_2  [R0201-SMT-TEST]  163.67 73.2 270 top
R452  *0_5%_2  [R0201-SMT-TEST]  163.34 79.69 270 top
R453  0_5%_2  [R0201-SMT-TEST]  166.77 78.8 0 top
R455  *Short_0201  [S0201]  162.58 79.69 270 top
R456  100K_1%_2  [R0201-SMT-TEST]  164.1 78.8 270 top
R457  *Short_0201  [S0201]  164.86 78.8 270 top
R458  30.1K_1%_2  [R0201-SMT-TEST]  164.74 73.2 270 top
R459  0_1%_4  [R0402]  161.25 79.63 0 top
R460  *Short_0402  [S0402]  159.52 79.95 0 top
R461  *Short_0201  [S0201]  128.64 81.52 270 top
R462  2.2_1%_6  [R0603]  161.05 71.69 0 top
R463  1K_1%_2  [R0201-SMT-TEST]  43.65 36.7 180 top
R464  1K_1%_2  [R0201-SMT-TEST]  42.03 44.99 270 top
R465  *0_5%_2  [R0201-SMT-TEST]  185.56 38.91 0 top
R466  100K_1%_2  [R0201-SMT-TEST]  185.51 42.95 0 top
R467  100K_1%_2  [R0201-SMT-TEST]  184.49 45.37 0 top
R468  1K_1%_2  [R0201-SMT-TEST]  92.8 44.86 0 bottom
R474  100K_1%_2  [R0201-SMT-TEST]  37.55 50.45 90 bottom
R488  0.05_1%_6  [R0603]  33.44 55.18 270 top
R491  0_1%_6  [R0603]  79.6 57.75 270 top
R570  5.1_1%_6  [R0603]  47.64 62.29 180 top
R595  10K_1%_2  [R0201-SMT-TEST]  105.43 72.96 90 bottom
R596  10K_1%_2  [R0201-SMT-TEST]  104.67 72.96 90 bottom
R937  4.7K_1%_4  [R0402]  152.01 21.27 270 bottom
R1000  0_5%_2  [R0201-SMT-TEST]  188.05 37.62 180 top
R1001  47K_1%_2  [R0201-SMT-TEST]  56.28 21.52 90 bottom
R1002  0_5%_4  [R0402]  51.85 8.5 270 top
R1003  6.98K_1%_4  [R0402]  57.17 13.14 0 bottom
R1004  4.7_1%_6  [R0603]  65.42 19.49 180 bottom
R1005  3.48K_1%_4  [R0402]  57.17 12.13 0 bottom
R1006  0_5%_4  [R0402]  56.82 18.1 270 top
R1007  0_5%_4  [R0402]  61.23 22.53 180 top
R1008  0.002_1%_12  [R1206]  179.09 68.29 0 top
R1009  133K_1%_2  [R0201-SMT-TEST]  60.66 14.34 180 top
R1010  0.05_1%_6  [R0603]  158.34 81.85 0 top
R1011  0_5%_4  [R0402]  52.62 12.98 0 top
R1012  10K_1%_4  [R0402]  66.57 15.84 180 top
R1013  *Short_0201  [S0201]  64.79 21.14 0 bottom
R1014  *Short_0201  [S0201]  139.46 72.89 90 top
R1016  0_1%_8  [R0805]  70.46 14.79 0 top
R1021  0.002_1%_12  [R1206]  49.19 46.73 180 top
R1022  1M_1%_2  [R0201-SMT-TEST]  169.56 18.17 0 top
R1023  1M_1%_2  [R0201-SMT-TEST]  169.56 22.75 0 top
R1024  1M_1%_2  [R0201-SMT-TEST]  169.56 21.98 0 top
R1026  *Short_0805  [S0805]  63.42 24.03 180 bottom
R1029  *2.2K_5%_2  [R0201-SMT-TEST]  95.65 65.09 270 bottom
R1030  *2.2K_5%_2  [R0201-SMT-TEST]  95.65 63.51 90 bottom
R3001  *0_5%_2  [R0201-SMT-TEST]  161.51 20.81 0 top
R3002  0_5%_2  [R0201-SMT-TEST]  160.17 21.09 180 top
R3003  *0_5%_2  [R0201-SMT-TEST]  163.11 24.98 0 top
R3004  0_5%_2  [R0201-SMT-TEST]  146.96 21.22 180 top
R3005  *0_5%_2  [R0201-SMT-TEST]  146.96 20.51 0 top
R3006  0_5%_2  [R0201-SMT-TEST]  163.11 25.69 180 top
R3803  100_1%_4  [R0402]  138.4 49.67 90 top
R3808  150_1%_2  [R0201-SMT-TEST]  96.86 49.05 180 top
R3809  100_1%_4  [R0402]  137.81 48.32 180 top
R3810  100_1%_4  [R0402]  137.71 51.4 270 top
R3812  200_1%_2  [R0201-SMT-TEST]  96.87 51.19 180 top
R3902  470_1%_2  [R0201-SMT-TEST]  92.47 41.67 180 top
R3903  *Short_0402  [S0402]  91.02 41.56 0 top
R4101  10M_1%_2  [R0201-SMT-TEST]  93.31 49.68 0 top
R4102  200K_1%_2  [R0201-SMT-TEST]  113.63 77.19 180 top
R4305  240_1%_2  [R0201-SMT-TEST]  143.12 41.56 90 top
R4306  240_1%_2  [R0201-SMT-TEST]  143.12 43.46 270 top
R4405  240_1%_2  [R0201-SMT-TEST]  131.95 42.66 0 top
R4406  240_1%_2  [R0201-SMT-TEST]  135.47 42.67 0 top
R4605  240_1%_2  [R0201-SMT-TEST]  118.09 42.63 180 top
R4606  240_1%_2  [R0201-SMT-TEST]  120.67 42.63 180 top
R4705  240_1%_2  [R0201-SMT-TEST]  109.14 35.75 270 top
R4706  240_1%_2  [R0201-SMT-TEST]  109.14 33.89 90 top
R8602  49.9_1%_4  [R0402]  125.93 79.01 90 top
R8603  1K_1%_2  [R0201-SMT-TEST]  122.94 83.91 0 top
R8604  1K_1%_2  [R0201-SMT-TEST]  118.73 77.12 270 top
R8606  499_1%_2  [R0201-SMT-TEST]  122.55 82.48 0 top
R8607  1K_1%_2  [R0201-SMT-TEST]  112.41 84.14 180 top
R8608  62_1%_4  [R0402]  112.54 83.25 0 top
R8609  *10K_1%_2  [R0201-SMT-TEST]  122.94 83.2 0 top
R8702  10K_1%_2  [R0201-SMT-TEST]  95.09 45.49 0 top
R11103  100K_1%_2  [R0201-SMT-TEST]  100.17 46.25 180 top
R11107  100K_1%_2  [R0201-SMT-TEST]  96.36 54.76 180 top
R11108  100K_1%_2  [R0201-SMT-TEST]  96.36 55.53 180 top
R11109  47K_1%_2  [R0201-SMT-TEST]  93.82 45.24 90 top
R11110  100K_1%_2  [R0201-SMT-TEST]  97.12 45.44 0 top
R11111  100K_1%_2  [R0201-SMT-TEST]  98.64 46.25 0 top
R11112  100K_1%_2  [R0201-SMT-TEST]  102.51 57.29 180 bottom
R11114  75K_1%_2  [R0201-SMT-TEST]  96.28 58.56 180 top
R11120  *75K_1%_2  [R0201-SMT-TEST]  96.1 57.81 90 bottom
R27106  *10K_1%_2  [R0201-SMT-TEST]  175.86 57.18 0 top
R27113  100_1%_2  [R0201-SMT-TEST]  177.38 49.68 90 top
R27115  6.2_5%_6  [R0603]  183.79 48.78 270 bottom
R27120  100_1%_4  [R0402]  142.74 67.08 270 top
R27121  100_1%_4  [R0402]  142.74 68.86 270 top
R27124  *0_5%_4  [R0402]  176.37 58.07 90 bottom
R27125  *0_5%_4  [R0402]  177.38 58.07 90 bottom
R27221  1_5%_8  [R0805]  161.89 53.62 90 top
R27222  *Short_0402  [S0402]  161 66.8 270 top
R27223  *Short_0402  [S0402]  159.98 66.8 270 top
R27288  2M_5%_2  [R0201-SMT-TEST]  34.35 69.4 180 top
R27289  2M_5%_2  [R0201-SMT-TEST]  34.35 70.18 180 top
R27291  100K_1%_2  [R0201-SMT-TEST]  155.39 21.36 270 bottom
R27292  *Short_0201  [S0201]  160.22 23.3 0 top
R27293  *10K_1%_2  [R0201-SMT-TEST]  146.96 24.78 0 top
R27294  *10K_1%_2  [R0201-SMT-TEST]  150.89 24.57 0 bottom
R27295  *10K_1%_2  [R0201-SMT-TEST]  146.93 18.68 0 top
R27296  *10K_1%_2  [R0201-SMT-TEST]  145.56 23.18 90 top
R27297  *10K_1%_2  [R0201-SMT-TEST]  146.96 22.47 0 top
R27298  *10K_1%_2  [R0201-SMT-TEST]  146.96 23.18 0 top
R27299  *10K_1%_2  [R0201-SMT-TEST]  146.93 19.39 0 top
R27300  *10K_1%_2  [R0201-SMT-TEST]  146.93 17.97 0 top
R27301  *10K_1%_2  [R0201-SMT-TEST]  149.88 25.67 0 bottom
R27302  100K_5%_2  [R0201-SMT-TEST]  27.04 59.27 180 top
R27303  100K_5%_2  [R0201-SMT-TEST]  26.38 60.03 180 top
R27304  100K_5%_2  [R0201-SMT-TEST]  26.4 60.74 180 top
R27305  29.4K_1%_4  [R0402]  19.83 59.93 0 top
R27306  48.7K_1%_4  [R0402]  19.83 60.89 0 top
R27307  100K_5%_2  [R0201-SMT-TEST]  24.13 57.13 0 top
R27308  *Short_0201  [S0201]  25.12 57.13 180 top
R27309  100K_1%_2  [R0201-SMT-TEST]  56.15 18.6 90 bottom
R27310  *Short_0201  [S0201]  94.35 62.55 0 top
R27311  *Short_0201  [S0201]  32.26 23.3 90 bottom
R27312  *0_5%_2  [R0201-SMT-TEST]  41.87 25.72 270 bottom
R27313  0_5%_4  [R0402]  46.75 65.21 180 top
R27330  *Short_0402  [S0402]  14.65 64.83 180 top
R91317  0_5%_2  [R0201-SMT-TEST]  96.67 24.14 0 top
R91318  *0_5%_2  [R0201-SMT-TEST]  96.67 23.38 0 top
R91319  *Short_0201  [S0201]  106.19 25.59 0 top
R91320  150_5%_4  [R0402]  98.44 24.27 180 top
R91321  *22K_1%_4  [R0402]  106.32 24.27 180 top
R91322  30K_1%_4  [R0402]  106.32 23.25 180 top
R91323  *Short_0201  [S0201]  94.73 60.21 180 top
R91324  0_5%_2  [R0201-SMT-TEST]  189.22 67.45 270 bottom
R91325  0_5%_2  [R0201-SMT-TEST]  189.98 67.45 270 bottom
R91326  *100K_1%_4  [R0402]  176.68 55.94 90 bottom
R91327  *0_5%_2  [R0201-SMT-TEST]  37.59 25.72 270 bottom
R91328  *0_5%_2  [R0201-SMT-TEST]  38.36 25.72 270 bottom
R91329  *Short_0201  [S0201]  22.18 18.48 180 top
R91330  0_5%_2  [R0201-SMT-TEST]  17.93 18.02 90 top
R91331  0_5%_2  [R0201-SMT-TEST]  17.21 18.02 90 top
R91332  *Short_0201  [S0201]  25.47 9.21 180 top
R91333  0_5%_2  [R0201-SMT-TEST]  20.69 9.97 90 top
R91334  0_5%_2  [R0201-SMT-TEST]  19.98 9.97 90 top
R91335  *Short_0201  [S0201]  23.63 32.86 180 top
R91336  *Short_0201  [S0201]  23.63 32.07 180 top
R91337  100K_1%_2  [R0201-SMT-TEST]  47.14 66.99 90 top
R91338  100_1%_6  [R0603]  43.58 68.26 180 top
R91339  *Short_0201  [S0201]  10.81 34.48 90 top
R91340  0_5%_2  [R0201-SMT-TEST]  35.32 68.22 180 bottom
R91341  0_5%_2  [R0201-SMT-TEST]  35.32 67.44 180 bottom
R91342  0_5%_2  [R0201-SMT-TEST]  106.06 68.77 90 bottom
R91343  1K_1%_2  [R0201-SMT-TEST]  91.71 20.89 90 bottom
R91345  *0_5%_2  [R0201-SMT-TEST]  36.17 66.8 90 bottom
R91346  *0_5%_2  [R0201-SMT-TEST]  36.21 68.9 270 bottom
R91347  0_5%_2  [R0201-SMT-TEST]  36.21 69.91 270 bottom
R91348  0_5%_2  [R0201-SMT-TEST]  35.32 66.67 0 bottom
R91349  0_5%_2  [R0201-SMT-TEST]  186.92 50.35 90 bottom
R91350  KBL@10_1%_6  [R0603]  75.14 13.65 0 top
R91351  *KBL@100K_1%_2  [R0201-SMT-TEST]  78.67 14.5 90 top
R91352  KBL@100K_1%_2  [R0201-SMT-TEST]  77.91 14.5 90 top
R91353  KBL@43.2K_1%_4  [R0402]  79.14 13.46 180 top
R91354  0_5%_4  [R0402]  15.36 20.92 180 top
R91355  0_5%_4  [R0402]  15.36 21.88 180 top
R91356  0_5%_4  [R0402]  19.96 12.13 270 top
R91357  0_5%_4  [R0402]  19.96 13.93 90 top
R91358  0_5%_2  [R0201-SMT-TEST]  18.81 18.65 90 top
R91359  *10K_5%_2  [R0201-SMT-TEST]  17.95 18.88 180 top
R91360  *10K_5%_2  [R0201-SMT-TEST]  16.96 18.88 0 top
R91361  0_5%_2  [R0201-SMT-TEST]  23.03 9.33 90 top
R91362  *10K_5%_2  [R0201-SMT-TEST]  21.4 9.97 90 top
R91363  *10K_5%_2  [R0201-SMT-TEST]  19.25 9.97 90 top
R91364  100K_1%_2  [R0201-SMT-TEST]  158.72 25.23 0 bottom
R91365  100K_1%_2  [R0201-SMT-TEST]  158.72 25.94 0 bottom
RB6B1  10K_1%_2  [R0201-SMT-TEST]  91.53 45.24 270 top
RT756  200_1%_4  [R0402]  95.65 51.8 270 top
RT854  200_1%_4  [R0402]  95.78 63.01 0 top
SW1  SW@A205-U-H2-1CTR  [SW-A205-U-H2-1CTR-3P]  3.75 5.4 270 top
TP1  *TP  [TP2050]  88.66 69.15 270 bottom
TP2  *TP  [TP2050]  90.95 71.86 0 bottom
TP3  *TP  [TP2050]  21.91 43.83 0 top
TP4  *TP  [TP2050]  44.4 15.33 270 top
TP6  *TP  [TP2050]  167.4 26.18 0 top
TP7  *TP  [TP2050]  166.01 25.03 0 top
TP8  *TP  [TP2050]  80.76 57.29 0 top
TP9  *TP  [TP2050]  89.98 37.17 0 top
TP10  *TP  [TP2050]  67.33 63.56 180 top
TP12  *TP  [TP2050]  117.11 66.74 180 bottom
TP13  *TP  [TP2050]  118.33 64.54 180 bottom
TP14  *TP  [TP2050]  123.46 64.43 180 bottom
TP15  *TP  [TP2050]  122.55 65.39 180 bottom
TP16  *TP  [TP2050]  120.87 60.22 180 bottom
TP17  *TP  [TP2050]  124.93 60.61 180 bottom
TP18  *TP  [TP2050]  126.45 61.11 180 bottom
TP19  *TP  [TP2050]  118.83 58.83 180 bottom
TP20  *TP  [TP2050]  119.6 60.22 180 bottom
TP21  *TP  [TP2050]  126.43 62.38 180 bottom
TP22  *TP  [TP2050]  124.93 62.38 180 bottom
TP23  *TP  [TP2050]  120.87 64.54 180 bottom
TP24  *TP  [TP2050]  127.09 59.97 180 bottom
TP25  *TP  [TP2050]  113.37 60.22 180 bottom
TP26  *TP  [TP2050]  112.1 60.22 180 bottom
TP27  *TP  [TP2050]  106.93 67.55 180 bottom
TP28  *TP  [TP2050]  109.14 67.91 180 bottom
TP29  *TP  [TP2050]  118.33 60.22 180 bottom
TP30  *TP  [TP2050]  109.69 60.86 180 bottom
TP31  *TP  [TP2050]  109.69 57.3 180 bottom
TP32  *TP  [TP2050]  110.83 60.22 180 bottom
TP33  *TP  [TP2050]  109.82 58.57 180 bottom
TP34  *TP  [TP2050]  126.26 77.74 0 top
TP35  *TP  [TP2050]  137.57 49.49 0 top
TP36  *TP  [TP2050]  134.55 49.76 180 bottom
TP37  *TP  [TP2050]  117.06 64.83 180 bottom
TP38  *TP  [TP2050]  114.32 70.78 180 bottom
TP39  *TP  [TP2050]  113.94 69.28 180 bottom
TP40  *TP  [TP2050]  113.91 66.56 180 bottom
TP41  *TP  [TP2050]  113.78 67.86 180 bottom
TP42  *TP  [TP2050]  94.02 53.25 0 top
TP43  *TP  [TP2050]  95.34 53.22 0 top
TP44  *TP  [TP2050]  115.02 60.22 180 bottom
TP45  *TP  [TP2050]  113.94 58.96 180 bottom
TP46  *TP  [TP2050]  109.19 78.07 0 top
TP47  *TP  [TP2050]  109.19 79.34 0 top
TP48  *TP  [TP2050]  105.17 55.84 180 bottom
TP49  *TP  [TP2050]  110.25 68.51 180 bottom
TP50  *TP  [TP2050]  110.15 67.12 180 bottom
TP51  *TP  [TP2050]  108.42 57.3 180 bottom
TP52  *TP  [TP2050]  118.15 78.47 0 top
TP53  *TP  [TP2050]  107.13 78.04 0 top
TP54  *TP  [TP2050]  119.6 64.54 180 bottom
TP55  *TP  [TP2050]  69.49 67.5 90 top
TP59  *TP  [TP2050]  119.04 80.3 0 top
TP60  *TP  [TP2050]  102.58 45.49 0 top
TP61  *TP  [TP2050]  103.85 45.37 0 top
TP62  *TP  [TP2050]  127.85 69.66 180 bottom
TP63  *TP  [TP2050]  130.12 77.99 0 top
TP64  *TP  [TP2050]  122.93 77.02 0 top
TP65  *TP  [TP2050]  122.77 71.78 180 bottom
TP66  *TP  [TP2050]  168.04 17.84 0 top
TP78  *TP  [TP2050]  97.68 44.44 0 top
TP86  *TP  [TP2050]  160.19 22.54 0 top
TP87  *TP  [TP2050]  153.94 25.97 180 bottom
TP93  *TP  [TP2050]  115.97 69.74 180 bottom
TP94  *TP  [TP2050]  115.97 71.01 180 bottom
TP95  *TP  [TP2050]  96.54 63.61 180 bottom
TP96  *TP  [TP2050]  96.54 64.88 180 bottom
TP97  *TP  [TP2050]  99.04 72.19 180 bottom
TP98  *TP  [TP2050]  104.21 66.15 180 bottom
TP99  *TP  [TP2050]  98.44 54.12 180 bottom
TP100  *TP  [TP2050]  97.05 62.88 0 top
TP101  *TP  [TP2050]  97.09 59.8 0 top
TP102  *TP  [TP2050]  105.93 63.69 180 bottom
TP103  *TP  [TP2050]  94.63 65.47 0 top
TP104  *TP  [TP2050]  94.13 64.07 0 top
TP105  *TP  [TP2050]  95.4 63.89 0 top
TP107  *TP  [TP2050]  147.86 17.9 0 top
TP108  *TP  [TP2050]  104.67 64.06 180 bottom
TP109  *TP  [TP2050]  104.46 74.92 180 bottom
TP110  *TP  [TP2050]  33.04 13.27 0 top
TP111  *TP  [TP2050]  33.04 14.67 0 top
TP112  *TP  [TP2050]  33.04 16.06 0 top
TP113  *TP  [TP2050]  97.66 66.56 180 bottom
TP114  *TP  [TP2050]  155.21 24.09 180 bottom
TP116  *TP  [TP2050]  191.14 80.51 0 top
TP118  *TP  [TP2050]  97.55 71.05 180 bottom
TP119  *TP  [TP2050]  98.82 70.92 180 bottom
TP120  *TP  [TP2050]  99.69 65.21 180 bottom
TP121  *TP  [TP2050]  103.78 71.18 180 bottom
TP122  *TP  [TP2050]  40.85 25.51 180 bottom
TP123  *TP  [TP2050]  41.36 26.86 180 bottom
TP125  *TP  [TP2050]  101.64 61.07 180 bottom
TP126  *TP  [TP2050]  104.07 61.39 180 bottom
TP127  *TP  [TP2050]  94.91 65.92 180 bottom
TP128  *TP  [TP2050]  96.19 66.12 180 bottom
TP129  *TP  [TP2050]  99.71 66.62 180 bottom
TP130  *TP  [TP2050]  103.95 80.25 0 top
TP131  *TP  [TP2050]  104.07 62.88 180 bottom
TP132  *TP  [TP2050]  100.6 63.54 180 bottom
U1  UR@TS3A27518ERTWR  [QFN24-4X4-5-25P-TS3A27518ERTWR]  171.16 28.09 90 top
U1JSL  CPU_JSL_1338P  [BGA1338-INTEL-JSL]  117.01 61.95 180 top
U2  ALC1015Q-CG  [QFN32-5X5-5-33P-ALC1015]  20.1 22.75 270 top
U3  ALC5682I-VD-CGT  [QFN40-5X5-4-41P-92HD99]  20.14 38.82 180 top
U4  ALC1015Q-CG  [QFN32-5X5-5-33P-ALC1015]  24.28 13.33 270 top
U5  KBL@SYV226POC  [BGA9-SILERGY-SYV226POC]  77.68 11.26 180 top
U6  PI3USB31532ZLCEX  [QFN40-6X3-4-41P-0_75H]  31.79 63.56 90 top
U7  PI3USB9201ZTAEX  [QFN12-2X2-4]  32.83 58.53 0 bottom
U8  TPD6S300ARUKR  [QFN20-3X3-4-21P-TPD6S300]  39.24 69.09 270 top
U9  RAA489000ARGNP#HA0  [QFN40-5X5-4-41P-1H]  61.61 18.07 270 top
U10  RT3612EGGQW  [QFN32-4X4-4-33P-RT8845B]  179.67 53.62 0 top
U11  GD25Q127CWIGR  [WSON8-6X5-1_27-9P-W25Q64FWZPIG]  175.75 26.2 0 bottom
U12  GT34C02B-2UDLI-TR  [DFN8-3X2-5-9P-GT24C256B]  161.94 29.91 180 top
U13  UR0605B-FT021  [BGA78-GOOGLE-UR0605B]  165.5 21.1 0 top
U14  H26M62002JPR  [BGA153-HYNIX-H26M62002JPR-0_5S]  66.21 45.69 90 top
U15  GS@BMI160  [LGA14-3X2_5-5]  168.8 72.58 270 bottom
U16  *74AUP1T97GM  [SON6-1_45X1-5-6P-0_5H]  36.39 28.05 90 bottom
U17  NPCX797FC0BX  [BGA144-NUVOTON-NPCX796F]  153.56 24.02 0 top
U18  0.01_1%_8  [R0805]  53.54 11.51 180 top
U19  0.01_1%_8  [R0805]  83.1 19.95 0 bottom
U21  RT6543AGQW  [QFN20-3X3-4-21P-RT6543B]  50.51 58.57 270 top
U22  RT8231AGQW  [WQFN20-3X3-4-21P]  181.83 40.67 0 top
U23  TPS22976DPUR  [SON14-3X2-4-15P-0_85H]  37.81 51.46 0 top
U24  TPS22971YZPR  [BGA8-TEXAS-TPS22971]  82.57 57.39 90 top
U26  TPS22971YZPR  [BGA8-TEXAS-TPS22971]  87.59 35.33 0 top
U27  TPS22971YZPR  [BGA8-TEXAS-TPS22971]  67.78 65.3 180 top
U30  RT6256BHGQUF  [QFN12-3X3-45-0_6H]  39.64 41.96 270 top
U31  RT6256CGQUF  [QFN12-3X3-45-0_6H]  40.32 32.87 270 top
U32  RT6219AHGQW  [DFN10-3X3-5-11P-RT9296]  74.26 25.43 270 top
U33  APW8738AQBI-TRG  [QFN16-3X3-5-17P-APW8738A]  59.27 36.48 90 top
U34  AP2553FDC-7  [DFN2020-6-2X2-65-7P]  18.92 29.27 270 top
U35  TS@RT9724GB  [TSOT23-5-2_7955-9395-5P]  32.15 50.86 180 top
U36  AP2121AK-1.8TRG1  [SOT23-2_8-95-5P-MAX834EUK-T]  176.93 27.06 90 top
U37  SLGC55545VTR  [QFN16-3X3-5-17P-SLGC55544C]  23.39 60.26 0 top
U38  RT6541AGQW  [DFN14-3X2-4-15P-0_8H]  163.16 76.1 180 top
U40  TPS22913CYZVR  [BGA4-TEXAS-TPS22912CYZVR-0_5S]  185.13 35.71 0 top
U41  74LVC1G04GW  [SOT353-2_1-65-5P-74LVC1G126]  165.5 31.18 90 bottom
U42  74LVC1G126GW  [SOT353-2_1-65-5P-74LVC1G126]  171.02 30.86 90 bottom
U4100  AX201.D2WG.NVW-MM#999TDN  [MODULE-12X16-152P-SMT]  39.1 16.5 90 bottom
U4301  H9HCNNNCPMALHR-NEE  [BGA200-HYNIX-H9HCNNNCPMMLXR-0_5S]  151.5 42.44 0 top
U4401  H9HCNNNCPMALHR-NEE  [BGA200-HYNIX-H9HCNNNCPMMLXR-0_5S]  133.31 34.3 270 top
U4601  H9HCNNNCPMALHR-NEE  [BGA200-HYNIX-H9HCNNNCPMMLXR-0_5S]  119.76 34.3 270 top
U4701  H9HCNNNCPMALHR-NEE  [BGA200-HYNIX-H9HCNNNCPMMLXR-0_5S]  100.75 34.71 180 top
U6581  TMP708AIDBVR  [SOT23-5-2_8-95-5P-G708]  102.25 24.52 0 top
U6582  GMR@HGDEDM013A  [SENSOR-1_3X0_9-5-4P]  14.3 67.65 90 top
Y4101  32.768KHZ/20ppm  [XTL-3_2X1_5-2_5-SMT]  93.18 51.08 180 top
Y4102  38.4Mhz/20ppm  [XTL-2X1_6-1_4X1_1-4P]  114.01 80.54 0 top

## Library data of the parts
C1 C1A6 C2 C3 C3C8 C3C9 C4-C85 C89 C90 C92 C96 C98 C102-C136 C139-C144 C148-C159 C161-C224 C226 C227 C230-C245 C248-C300 C305-C310 C313-C377 C379 C380 C382 C386-C407 C412-C414 C416 C418 C419 C422 C424 C426 C474 C486-C489 C491 C502-C504 C583 C587 C1000 C1002-C1018 C1025 C1027 C1028 C1035 C1036 C1045 C3205 C3208 C3210 C3213 C3216 C3406 C3423 C3501 C3504 C3508 C3512 C3514 C3517 C3522 C3526 C3530 C3531 C3535 C3562-C3564 C3609 C4101-C4104 C4301 C4401 C4501-C4541 C4601 C4701 C4801-C4841 C27101 C27102 C27104 C27218 C27220 C27222 C27224 C27226 C27228 C27230 C28002-C28004 C28006-C28011 C28015-C28026 = CAP_NON-POL_BGM
C137 C138 C145 C146 C1001 = CAP_NON-POL_V1_BGM
C160 C378 C381 C28005 = CAP_POL_BGM
C10711 = CAP NON-POL_BGM
CN2 = FFCFPC_4P_2F_BGM
CR1-CR7 D11-D15 D2743 D2748 = TVS_DIODE_BGM
D1-D4 D16 D17 = TPD4E101DPWR_BGM
D5 D7 D8 = PUSB3F96_10P_BGM
D9 D26 = BAT54C_BGM
D10 D18-D23 D27-D36 D38-D40 D1000 D1001 D2744 D2747 = Schottky_DIODE_BGM
D24 = Schottky_DIODE_V2_BGM
D25 D2745 D2746 = TVS_DIODE_UNI_V2_BGM
D2741 D2742 = PESD5V0X2UM_BGM
DS1 = LED_6P_GRB_BGM
F1 = FUSE
FB1 = BEAD_BGM
HOLE1 HOLE2 HOLE17-HOLE23 HOLE25-HOLE29 HOLE32 HOLE34-HOLE36 HOLE38-HOLE46 = 3x2_6.1
J1 J2 = DIP_HEADER_2P_BGM
J3 = Header_8P_2R_BGM
J4 = Header_4P_BGM
J9 = CN9+4-TF_0
J10 = USB3_TCR26-9V1391_13P_BGM
J11 = USB3_1_24P_8F_BGM
J12 = FFCFPC_20P_BGM
J13 = FFCFPC_50P_BGM
J14 = HEADER 5_0
J15 = HOUSING_60P_2R_6F_BGM
J16 = COMBOJACK_7P_BGM_0
J17 J25 = FFCFPC_30P_BGM
J18 = FFCFPC_6P_V2_BGM
J23 = FFCFPC_40P_BGM
J24 = Housing_6P_BGM
L1-L8 = BW_BGM
L9 L10 L12 = IND_V2_BGM
L11 L13-L17 L3601 L27203 = INDUCTOR_BGM
L27202 = IND_BGM
Q2 Q1000 = MOS-N_8P_SCH_BGM
Q3 Q30-Q33 = MOS-N_8P_V3_BGM
Q4 Q5 Q9 Q10 Q12-Q15 Q17 Q19-Q22 Q24-Q27 Q36-Q38 Q1002 Q1010 = MOS-N_3P_ESD_BGM
Q6 = MOS-P_3P_BGM
Q16 Q18 Q23 Q28 = MOS-P_3P_ESD_V3_BGM
Q34 Q35 Q1001 Q1008 = MOS-N-Dual_9P_BGM
Q1009 = MOS-N_3P_ESD_V2_BGM
R1 R1G1 R1G3 R1H18 R2 R2C20 R2F1 R3 R3C14 R3C18 R3C22 R3C23 R3F3 R3F4 R4 R4E63 R4F20 R4F23 R5 R5F9 R5G69 R5M19 R6 R6C1 R6D29 R6D34 R6D38-R6D42 R6D46 R6D66 R6D67 R6D82 R6D84 R6D85 R6D88 R6E3 R6E5 R6F1 R6F3 R7D9 R7D24-R7D26 R7D35 R7D40 R8 R8A7 R9 R11 R12 R17 R20-R38 R40-R80 R84 R88 R89 R95 R98 R99 R102 R103 R105 R107 R109-R114 R116-R121 R123 R125 R126 R128-R168 R170-R180 R183-R188 R191-R196 R199-R202 R204-R237 R239 R241 R242 R246 R249 R251 R253-R257 R260-R265 R269-R273 R275 R277-R289 R291-R299 R301 R302 R305 R311 R314-R320 R322 R324-R341 R343-R347 R352-R355 R357 R360 R362-R365 R368 R370-R373 R375 R377-R387 R389-R394 R397-R399 R402-R420 R422-R433 R435 R437-R453 R456 R458 R459 R462-R468 R474 R488 R491 R570 R595 R596 R937 R1000-R1007 R1009-R1012 R1016 R1022-R1024 R1029 R1030 R3001-R3006 R3803 R3808-R3810 R3812 R3902 R4101 R4102 R4305 R4306 R4405 R4406 R4605 R4606 R4705 R4706 R8602-R8604 R8606-R8609 R8702 R11103 R11107-R11112 R11114 R11120 R27106 R27113 R27115 R27120 R27121 R27124 R27125 R27221 R27288 R27289 R27291 R27293-R27307 R27309 R27312 R27313 R91320-R91322 R91324-R91328 R91330 R91331 R91333 R91334 R91337 R91338 R91340-R91343 R91345-R91365 RB6B1 RT756 RT854 = RES_BGM
R2F3 R2F14 R3F13 R10 R13 R18 R19 R39 R81-R83 R85-R87 R90-R94 R96 R97 R169 R181 R182 R189 R190 R203 R240 R290 R300 R303 R313 R356 R366 R367 R369 R395 R400 R401 R434 R436 R455 R457 R460 R461 R1013 R1014 R1026 R3903 R27222 R27223 R27292 R27308 R27310 R27311 R27330 R91319 R91323 R91329 R91332 R91335 R91336 R91339 = SHORTPAD_V01_BGM
R7 R238 R243-R245 R247 R248 R250 R252 R258 R259 R266 R267 R276 R304 R1008 R1021 U18 U19 = R_Current_SEN_BGM
R268 R274 R321 R323 = Thermistor_BGM
R91317 R91318 = RES_BGM_0
SW1 = SW_TAFG1_7P_BGM
TP1-TP4 TP6 TP7 TP12-TP54 TP59-TP66 TP78 TP86 TP87 TP93-TP105 TP107-TP114 TP116 TP118-TP123 TP125-TP132 = TP_BGM
TP8-TP10 TP55 = PAD_1
U1 = TS3A27518ERTWR_24P_BGM
U1JSL = CPU_JSL_1338P_BGM
U2 U4 = ALC1015-CG_32P_V3_BGM
U3 = ALC56821-CGT_40P_V2_BGM
U5 = SYV226POC_9P_BGM
U6 = PI3USB31532ZLEX_40P_BGM
U7 = PI3USB9201ZTAEX_12P_V1_BGM
U8 = TPD6S300ARUKR_20P_BGM
U9 = ISL9237_19
U10 = RT3612EBGQW-02_32P_BGM_1
U11 = W25Q80DVZPIG_8P_WON_BGM
U12 = AT24C02C-MAHM-T_8P_BGM
U13 = UR0605B-FT021_78P_V2_BGM_0
U14 = EMMC_153P_BGM_1
U15 = BMI160_2
U16 = 74AUP1T97GM_6P_BGM
U17 = NPCX796FC0BX_144P_BGM
U21 = RT6543BGQW_20P_BGM_5
U22 = RT8231AGQW_20P_BGM_7
U23 = TPS22976DPUR_14P_V1_BGM_0
U24 = TPS22971YZPR_8P_BGM_0
U26 U27 = TPS22971YZPR_8P_BGM_1
U30 = RT6256BGQUF_12P_BGM_0
U31 = RT6256CGQUF_12P_BGM_0
U32 = RT6219AHGQW_11P_BGM_2
U33 = APW8738AQBI-TRG_16P_BGM_7
U34 = AP2553FDC-7_6P_BGM_2
U35 = RT9742QGJ5_5P_BGM_1
U36 = RT9020-18GB_5P_BGM_1
U37 = SLGC55545VTR_16P_BGM
U38 = RT6541AGQW_14P_BGM_3
U40 = TPS22913CYZVR_4P_BGM
U41 = SN74LVC1G07DBVR_5P_BGM
U42 = 74LVC1G126SE-7_5P_BGM
U4100 = AC-9560_152P_V02_BGM
U4301 U4401 U4601 U4701 = LPDDR4
U6581 = LM86_1
U6582 = ME268-002_0
Y4101 = CRYSTAL_2P_BGM
Y4102 = CRYSTAL_4P_BGM

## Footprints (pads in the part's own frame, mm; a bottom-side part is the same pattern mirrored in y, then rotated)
2D-BARCODE-8X8-S
  round 0.991 smd: 1(7,-4)
18-6056-01-2P-L
  round 1.626 hole 1.016: 1(-1.27,0) 2(1.27,0)
50208-00601-V02-6P-L
  rect 0.508x0.991 smd: 1(-2,1.95) 2(-1.2,1.95) 3(-0.4,1.95) 4(0.4,1.95) 5(1.2,1.95) 6(2,1.95)
  rect 1.194x1.702 smd: 7(-3.3,0) 8(3.3,0)
50505-00401-V01-4P-L
  rect 0.61x1.295 smd: 1(-1.5,3.25) 2(-0.5,3.25) 3(0.5,3.25) 4(1.5,3.25)
  rect 0.991x2.007 smd: 5(-4.1,0) 6(4.1,0)
50696-0200M-V02-20P-L
  rect 0.305x0.787 smd: 1(-4.75,2.5) 2(-4.25,2.5) 3(-3.75,2.5) 4(-3.25,2.5) 5(-2.75,2.5) 6(-2.25,2.5) 7(-1.75,2.5) 8(-1.25,2.5) 9(-0.75,2.5) 10(-0.25,2.5) 11(0.25,2.5) 12(0.75,2.5) 13(1.25,2.5) 14(1.75,2.5) 15(2.25,2.5) 16(2.75,2.5) 17(3.25,2.5) 18(3.75,2.5) 19(4.25,2.5) 20(4.75,2.5)
  rect 0.406x0.787 smd: 21(-5.75,0) 22(5.75,0)
51693-04001-V01-40P-L
  rect 0.305x1.295 smd: 1(-9.75,5.65) 2(-9.25,5.65) 3(-8.75,5.65) 4(-8.25,5.65) 5(-7.75,5.65) 6(-7.25,5.65) 7(-6.75,5.65) 8(-6.25,5.65) 9(-5.75,5.65) 10(-5.25,5.65) 11(-4.75,5.65) 12(-4.25,5.65) 13(-3.75,5.65) 14(-3.25,5.65) 15(-2.75,5.65) 16(-2.25,5.65) 17(-1.75,5.65) 18(-1.25,5.65) 19(-0.75,5.65) 20(-0.25,5.65) 21(0.25,5.65) 22(0.75,5.65) 23(1.25,5.65) 24(1.75,5.65) 25(2.25,5.65) 26(2.75,5.65) 27(3.25,5.65) 28(3.75,5.65) 29(4.25,5.65) 30(4.75,5.65) 31(5.25,5.65) 32(5.75,5.65) 33(6.25,5.65) 34(6.75,5.65) 35(7.25,5.65) 36(7.75,5.65) 37(8.25,5.65) 38(8.75,5.65) 39(9.25,5.65) 40(9.75,5.65)
  rect 1.803x2.21 smd: 41(-11.9,0) 42(11.9,0)
BGA4-TEXAS-TPS22912CYZVR-0_5S
  round 0.254 smd: A1(-0.25,-0.25) A2(-0.25,0.25) B1(0.25,-0.25) B2(0.25,0.25)
BGA8-TEXAS-TPS22971
  round 0.254 smd: A1(-0.75,-0.25) A2(-0.75,0.25) B1(-0.25,-0.25) B2(-0.25,0.25) C1(0.25,-0.25) C2(0.25,0.25) D1(0.75,-0.25) D2(0.75,0.25)
BGA9-SILERGY-SYV226POC
  round 0.254 smd: A1(-0.4,-0.4) A2(-0.4,0) A3(-0.4,0.4) B1(0,-0.4) B2(0,0) B3(0,0.4) C1(0.4,-0.4) C2(0.4,0) C3(0.4,0.4)
BGA78-GOOGLE-UR0605B
  round 0.254 smd: A1(-2,-2) A2(-2,-1.5) A3(-2,-1) A4(-2,-0.5) A5(-2,0) A6(-2,0.5) A7(-2,1) A8(-2,1.5) A9(-2,2) B1(-1.5,-2) B2(-1.5,-1.5) B3(-1.5,-1) B4(-1.5,-0.5) B5(-1.5,0) B6(-1.5,0.5) B7(-1.5,1) B8(-1.5,1.5) B9(-1.5,2) C1(-1,-2) C2(-1,-1.5) C3(-1,-1) C4(-1,-0.5) C5(-1,0) C7(-1,1) C8(-1,1.5) C9(-1,2) D1(-0.5,-2) D2(-0.5,-1.5) D4(-0.5,-0.5) D5(-0.5,0) D6(-0.5,0.5) D7(-0.5,1) D8(-0.5,1.5) D9(-0.5,2) E1(0,-2) E2(0,-1.5) E3(0,-1) E4(0,-0.5) E5(0,0) E6(0,0.5) E7(0,1) E8(0,1.5) E9(0,2) F1(0.5,-2) F2(0.5,-1.5) F3(0.5,-1) F4(0.5,-0.5) F5(0.5,0) F6(0.5,0.5) F7(0.5,1) F8(0.5,1.5) F9(0.5,2) G1(1,-2) G2(1,-1.5) G3(1,-1) G5(1,0) G6(1,0.5) G7(1,1) G8(1,1.5) G9(1,2) H1(1.5,-2) H2(1.5,-1.5) H3(1.5,-1) H4(1.5,-0.5) H5(1.5,0) H6(1.5,0.5) H7(1.5,1) H8(1.5,1.5) H9(1.5,2) J1(2,-2) J2(2,-1.5) J3(2,-1) J4(2,-0.5) J5(2,0) J6(2,0.5) J7(2,1) J8(2,1.5) J9(2,2)
BGA144-NUVOTON-NPCX796F
  round 0.3 smd: A1(-3.575,-3.575) A2(-3.575,-2.925) A3(-3.575,-2.275) A4(-3.575,-1.625) A5(-3.575,-0.975) A6(-3.575,-0.325) A7(-3.575,0.325) A8(-3.575,0.975) A9(-3.575,1.625) A10(-3.575,2.275) A11(-3.575,2.925) A12(-3.575,3.575) B1(-2.925,-3.575) B2(-2.925,-2.925) B3(-2.925,-2.275) B4(-2.925,-1.625) B5(-2.925,-0.975) B6(-2.925,-0.325) B7(-2.925,0.325) B8(-2.925,0.975) B9(-2.925,1.625) B10(-2.925,2.275) B11(-2.925,2.925) B12(-2.925,3.575) C1(-2.275,-3.575) C2(-2.275,-2.925) C3(-2.275,-2.275) C4(-2.275,-1.625) C5(-2.275,-0.975) C6(-2.275,-0.325) C7(-2.275,0.325) C8(-2.275,0.975) C9(-2.275,1.625) C10(-2.275,2.275) C11(-2.275,2.925) C12(-2.275,3.575) D1(-1.625,-3.575) D2(-1.625,-2.925) D3(-1.625,-2.275) D4(-1.625,-1.625) D5(-1.625,-0.975) D6(-1.625,-0.325) D7(-1.625,0.325) D8(-1.625,0.975) D9(-1.625,1.625) D10(-1.625,2.275) D11(-1.625,2.925) D12(-1.625,3.575) E1(-0.975,-3.575) E2(-0.975,-2.925) E3(-0.975,-2.275) E4(-0.975,-1.625) E5(-0.975,-0.975) E6(-0.975,-0.325) E7(-0.975,0.325) E8(-0.975,0.975) E9(-0.975,1.625) E10(-0.975,2.275) E11(-0.975,2.925) E12(-0.975,3.575) F1(-0.325,-3.575) F2(-0.325,-2.925) F3(-0.325,-2.275) F4(-0.325,-1.625) F5(-0.325,-0.975) F6(-0.325,-0.325) F7(-0.325,0.325) F8(-0.325,0.975) F9(-0.325,1.625) F10(-0.325,2.275) F11(-0.325,2.925) F12(-0.325,3.575) G1(0.325,-3.575) G2(0.325,-2.925) G3(0.325,-2.275) G4(0.325,-1.625) G5(0.325,-0.975) G6(0.325,-0.325) G7(0.325,0.325) G8(0.325,0.975) G9(0.325,1.625) G10(0.325,2.275) G11(0.325,2.925) G12(0.325,3.575) H1(0.975,-3.575) H2(0.975,-2.925) H3(0.975,-2.275) H4(0.975,-1.625) H5(0.975,-0.975) H6(0.975,-0.325) H7(0.975,0.325) H8(0.975,0.975) H9(0.975,1.625) H10(0.975,2.275) H11(0.975,2.925) H12(0.975,3.575) J1(1.625,-3.575) J2(1.625,-2.925) J3(1.625,-2.275) J4(1.625,-1.625) J5(1.625,-0.975) J6(1.625,-0.325) J7(1.625,0.325) J8(1.625,0.975) J9(1.625,1.625) J10(1.625,2.275) J11(1.625,2.925) J12(1.625,3.575) K1(2.275,-3.575) K2(2.275,-2.925) K3(2.275,-2.275) K4(2.275,-1.625) K5(2.275,-0.975) K6(2.275,-0.325) K7(2.275,0.325) K8(2.275,0.975) K9(2.275,1.625) K10(2.275,2.275) K11(2.275,2.925) K12(2.275,3.575) L1(2.925,-3.575) L2(2.925,-2.925) L3(2.925,-2.275) L4(2.925,-1.625) L5(2.925,-0.975) L6(2.925,-0.325) L7(2.925,0.325) L8(2.925,0.975) L9(2.925,1.625) L10(2.925,2.275) L11(2.925,2.925) L12(2.925,3.575) M1(3.575,-3.575) M2(3.575,-2.925) M3(3.575,-2.275) M4(3.575,-1.625) M5(3.575,-0.975) M6(3.575,-0.325) M7(3.575,0.325) M8(3.575,0.975) M9(3.575,1.625) M10(3.575,2.275) M11(3.575,2.925) M12(3.575,3.575)
